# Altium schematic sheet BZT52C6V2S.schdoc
size 127 x 101 mm
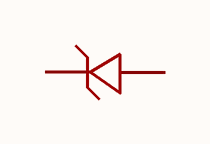
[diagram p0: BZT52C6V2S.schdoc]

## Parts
D?  bzt52c6v2s_c14645  [SOD-323_L1.8-W1.3-LS2.5-RD]  (value not drawn)

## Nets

Not connected (* = marked no-connect by the designer): D? 1(K) 2(A)

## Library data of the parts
D? = bzt52c6v2s_c14645: 二极管配置:1个独立式;稳压值(标称值):6.2V;稳压值(范围):5.8V~6.6V;耗散功率(Pd):200mW;; Manufacturer: CJ(江苏长电/长晶); AddInBom: yes; ModelId: db63db13d9e342eb939127d413d6200b; ModelTransform: 104.3305,51.181,0,0,0,0,0,-0.004,0; Diode Configuration: 1个独立式; Zener Voltage(Nom): 6.2V; Reverse Leakage Current (Ir): 3uA@1V; Pd - Power Dissipation: 200mW; Impedance(Zzt): 10Ω; Impedance(Zzk): 150Ω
